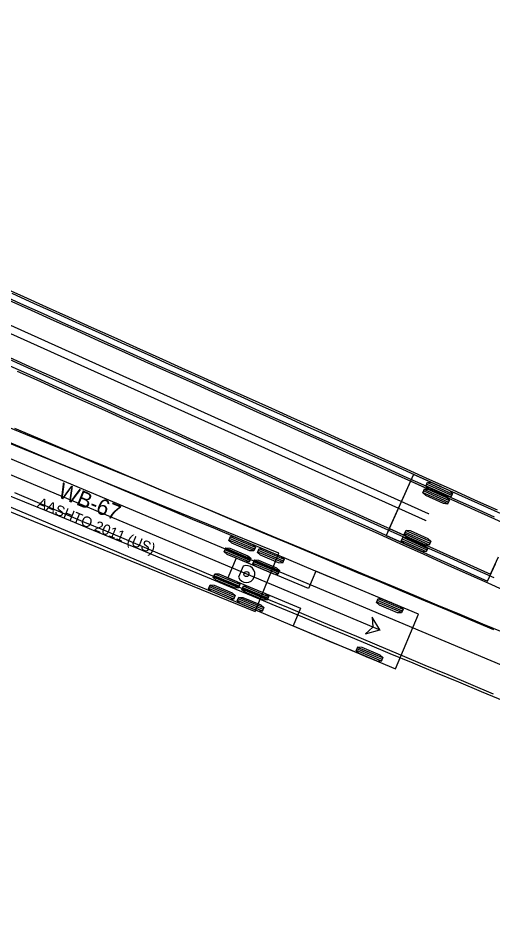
# Model space of a CAD drawing. Extents: x 916040 to 917457, y 328936 to 330267.
# Drawn here: x 917082.1 to 917146.2, y 329502 to 329623.8 of the extents above; entities that cross this region are included whole.
import ezdxf

# ---------------------------------------------------------------- set-up
doc = ezdxf.new("R2010")
doc.units = 0
for name, color, linetype in [('NB_RightontoRoute25_WB67', 7, 'Continuous'), ('NB_ThruontoManchester_WB67', 7, 'Continuous'), ('SB_LeftontoRoute25_WB67', 7, 'Continuous'), ('WB_LeftontoSaco_WB67', 7, 'Continuous'), ('WB_RightontoManchester_WB67', 7, 'Continuous'), ('WB_Thru_WB67', 7, 'Continuous')]:
    doc.layers.add(name, color=color, linetype=linetype)

msp = doc.modelspace()

# ---------------------------------------------------------------- linework, layer by layer
at = {"layer": 'NB_RightontoRoute25_WB67'}
msp.add_line((917062.28, 329572.24), (917451.54, 329408.71), dxfattribs=at)
for points in [[(917080.05, 329568.92), (917083.14, 329567.65), (917086.23, 329566.39), (917089.31, 329565.12), (917092.4, 329563.85), (917095.48, 329562.58), (917098.57, 329561.3), (917101.65, 329560.03), (917104.74, 329558.75), (917107.82, 329557.48), (917110.9, 329556.2), (917113.98, 329554.92), (917117.06, 329553.64), (917120.14, 329552.36), (917123.22, 329551.08), (917126.3, 329549.8), (917129.38, 329548.52), (917132.46, 329547.23), (917135.54, 329545.95), (917138.62, 329544.66), (917141.7, 329543.38), (917144.78, 329542.09), (917147.85, 329540.81)], [(917081.65, 329568.44), (917084.73, 329567.15), (917087.8, 329565.86), (917090.88, 329564.57), (917093.95, 329563.27), (917097.03, 329561.98), (917100.11, 329560.69), (917103.18, 329559.4), (917106.26, 329558.11), (917109.33, 329556.81), (917112.41, 329555.52), (917115.48, 329554.23), (917118.56, 329552.94), (917121.63, 329551.65), (917124.71, 329550.35), (917127.78, 329549.06), (917130.86, 329547.77), (917133.93, 329546.48), (917137.01, 329545.19), (917140.08, 329543.9), (917143.16, 329542.6), (917146.23, 329541.31)], [(917079.91, 329559.79), (917083, 329558.52), (917086.08, 329557.26), (917089.16, 329555.99), (917092.24, 329554.72), (917095.32, 329553.45), (917098.41, 329552.17), (917101.49, 329550.9), (917104.56, 329549.62), (917107.64, 329548.35), (917110.72, 329547.07), (917113.8, 329545.79), (917116.88, 329544.51), (917119.96, 329543.23), (917123.04, 329541.95), (917126.11, 329540.67), (917129.19, 329539.39), (917132.27, 329538.1), (917135.35, 329536.82), (917138.42, 329535.53), (917141.5, 329534.25), (917144.58, 329532.96), (917147.65, 329531.68)], [(917081.65, 329559.77), (917084.72, 329558.48), (917087.8, 329557.18), (917090.87, 329555.89), (917093.94, 329554.6), (917097.02, 329553.31), (917100.09, 329552.02), (917103.17, 329550.73), (917106.24, 329549.44), (917109.31, 329548.14), (917112.39, 329546.85), (917115.46, 329545.56), (917118.54, 329544.27), (917121.61, 329542.98), (917124.69, 329541.69), (917127.76, 329540.4), (917130.83, 329539.1), (917133.91, 329537.81), (917136.98, 329536.52), (917140.06, 329535.23), (917143.13, 329533.94), (917146.21, 329532.65)]]:
    msp.add_lwpolyline(points, dxfattribs=at)
at = {"layer": 'NB_ThruontoManchester_WB67'}
msp.add_line((917062.28, 329572.24), (917451.54, 329408.71), dxfattribs=at)
at = {"layer": 'SB_LeftontoRoute25_WB67'}
for p, q in [((917117.3, 329551.6), (917068.21, 329571.59)), ((917061.51, 329570.4), (917130.9, 329541.25)), ((917065.01, 329563.72), (917114.09, 329543.73)), ((917114.04, 329552.16), (917110.66, 329553.58)), ((917114.13, 329552.37), (917110.75, 329553.79)), ((917113.49, 329550.85), (917110.11, 329552.27)), ((917113.95, 329551.95), (917110.57, 329553.37)), ((917113.31, 329550.43), (917109.93, 329551.85)), ((917113.4, 329550.64), (917110.02, 329552.06)), ((917114.09, 329543.73), (917117.3, 329551.6)), ((917117.82, 329550.33), (917114.44, 329551.75)), ((917117.91, 329550.54), (917114.53, 329551.96)), ((917118, 329550.75), (917114.62, 329552.17)), ((917117.3, 329551.6), (917117.3, 329551.6)), ((917111.53, 329550.93), (917110.42, 329548.29)), ((917121.31, 329546.83), (917111.53, 329550.93)), ((917112.48, 329549.85), (917111.86, 329548.36)), ((917117.19, 329548.8), (917113.81, 329550.22)), ((917117.27, 329549.02), (917113.89, 329550.44)), ((917117.36, 329549.23), (917113.98, 329550.65)), ((917112.03, 329547.36), (917108.65, 329548.78)), ((917122.3, 329549.19), (917121.31, 329546.83)), ((917136.13, 329543.39), (917122.3, 329549.19)), ((917111.85, 329546.94), (917108.47, 329548.36)), ((917111.94, 329547.15), (917108.56, 329548.57)), ((917110.42, 329548.29), (917120.2, 329544.18)), ((917111.21, 329545.42), (917107.83, 329546.84)), ((917111.3, 329545.63), (917107.92, 329547.05)), ((917111.39, 329545.84), (917108.01, 329547.26)), ((917115.72, 329545.32), (917112.34, 329546.74)), ((917115.81, 329545.53), (917112.43, 329546.95)), ((917115.9, 329545.74), (917112.52, 329547.16)), ((917115.08, 329543.8), (917111.7, 329545.21)), ((917115.17, 329544.01), (917111.79, 329545.43)), ((917115.26, 329544.22), (917111.88, 329545.64)), ((917133.87, 329543.59), (917130.49, 329545.01)), ((917133.96, 329543.8), (917130.58, 329545.22)), ((917134.05, 329544.01), (917130.67, 329545.43)), ((917120.2, 329544.18), (917119.21, 329541.82)), ((917133.04, 329536.01), (917136.13, 329543.39)), ((917136.13, 329543.39), (917136.13, 329543.39)), ((917119.21, 329541.82), (917133.04, 329536.01)), ((917131.3, 329537.48), (917127.92, 329538.9)), ((917131.13, 329537.06), (917127.75, 329538.48)), ((917131.22, 329537.27), (917127.83, 329538.69))]:
    msp.add_line(p, q, dxfattribs=at)
for points in [[(917080.93, 329566.58), (917084.01, 329565.28), (917087.1, 329563.98), (917090.19, 329562.69), (917093.27, 329561.39), (917096.36, 329560.1), (917099.44, 329558.8), (917102.53, 329557.5), (917105.61, 329556.21), (917108.7, 329554.91), (917111.78, 329553.62), (917114.86, 329552.32), (917117.95, 329551.02), (917121.03, 329549.73), (917124.12, 329548.43), (917127.2, 329547.14), (917130.29, 329545.84), (917132.44, 329544.94)], [(917080.94, 329557.9), (917084.02, 329556.6), (917087.1, 329555.31), (917090.19, 329554.01), (917093.27, 329552.72), (917096.35, 329551.42), (917099.44, 329550.12), (917102.52, 329548.83), (917105.6, 329547.53), (917108.69, 329546.24), (917111.77, 329544.94), (917114.85, 329543.65), (917117.94, 329542.35), (917121.02, 329541.06), (917124.1, 329539.76), (917127.19, 329538.47), (917129.35, 329537.56)]]:
    msp.add_lwpolyline(points, dxfattribs=at)
for points in [[(917114.15, 329552.43), (917113.93, 329551.9), (917113.39, 329551.94), (917110.96, 329552.96), (917110.55, 329553.32), (917110.77, 329553.85), (917111.31, 329553.81), (917113.74, 329552.78)], [(917113.51, 329550.91), (917113.29, 329550.38), (917112.75, 329550.42), (917110.32, 329551.44), (917109.91, 329551.8), (917110.13, 329552.32), (917110.67, 329552.29), (917113.11, 329551.26)], [(917118.02, 329550.8), (917117.8, 329550.27), (917117.26, 329550.31), (917114.83, 329551.34), (917114.42, 329551.69), (917114.64, 329552.22), (917115.18, 329552.18), (917117.62, 329551.16)], [(917117.39, 329549.28), (917117.16, 329548.75), (917116.62, 329548.79), (917114.19, 329549.81), (917113.78, 329550.17), (917114, 329550.7), (917114.54, 329550.66), (917116.98, 329549.64)], [(917112.05, 329547.42), (917111.83, 329546.89), (917111.29, 329546.93), (917108.85, 329547.95), (917108.45, 329548.31), (917108.67, 329548.84), (917109.21, 329548.8), (917111.64, 329547.77)], [(917111.41, 329545.9), (917111.19, 329545.37), (917110.65, 329545.41), (917108.21, 329546.43), (917107.81, 329546.79), (917108.03, 329547.32), (917108.57, 329547.28), (917111, 329546.25)], [(917115.92, 329545.79), (917115.7, 329545.26), (917115.16, 329545.3), (917112.73, 329546.33), (917112.32, 329546.68), (917112.54, 329547.21), (917113.08, 329547.17), (917115.51, 329546.15)], [(917115.28, 329544.27), (917115.06, 329543.74), (917114.52, 329543.78), (917112.09, 329544.8), (917111.68, 329545.16), (917111.9, 329545.69), (917112.44, 329545.65), (917114.88, 329544.63)], [(917134.07, 329544.07), (917133.85, 329543.54), (917133.31, 329543.58), (917130.87, 329544.6), (917130.47, 329544.96), (917130.69, 329545.49), (917131.23, 329545.45), (917133.66, 329544.42)], [(917130.9, 329541.25), (917129.9, 329542.98), (917129.97, 329541.63), (917128.96, 329540.74)], [(917131.33, 329537.53), (917131.1, 329537.01), (917130.56, 329537.05), (917128.13, 329538.07), (917127.72, 329538.43), (917127.95, 329538.96), (917128.49, 329538.92), (917130.92, 329537.89)]]:
    msp.add_lwpolyline(points, close=True, dxfattribs=at)
for centre, radius in [((917112.92, 329548.79), 0.34), ((917132.44, 329544.94), 0.0417), ((917130.9, 329541.25), 0.0417), ((917129.35, 329537.56), 0.0417)]:
    msp.add_circle(centre, radius, dxfattribs=at)
msp.add_arc((917112.92, 329548.79), 1.14, 202.2286, 112.2286, dxfattribs=at)
at = {"layer": 'WB_LeftontoSaco_WB67'}
for p, q in [((917137.05, 329556.02), (916988.64, 329622.84)), ((917135.04, 329561.31), (917131.76, 329554.01)), ((917148.72, 329555.15), (917135.04, 329561.31)), ((917136.73, 329559.79), (917140.08, 329558.29)), ((917136.83, 329560), (917140.17, 329558.49)), ((917136.92, 329560.21), (917140.27, 329558.7)), ((917131.76, 329554.01), (917145.43, 329547.85)), ((917131.76, 329554.01), (917131.76, 329554.01)), ((917133.92, 329553.54), (917137.26, 329552.04)), ((917134.01, 329553.75), (917137.36, 329552.25)), ((917133.83, 329553.33), (917137.17, 329551.83)), ((917145.43, 329547.85), (917146.49, 329550.19))]:
    msp.add_line(p, q, dxfattribs=at)
for points in [[(917146.36, 329556.48), (917143.32, 329557.85), (917140.28, 329559.22), (917137.24, 329560.59), (917134.2, 329561.96), (917131.16, 329563.33), (917128.12, 329564.7), (917125.08, 329566.07), (917122.03, 329567.44), (917118.99, 329568.81), (917115.95, 329570.18), (917112.91, 329571.55), (917109.87, 329572.92), (917106.83, 329574.29), (917103.79, 329575.66), (917100.75, 329577.02), (917097.71, 329578.39), (917094.66, 329579.76), (917091.62, 329581.13), (917088.58, 329582.5), (917085.54, 329583.87), (917082.5, 329585.24), (917079.46, 329586.61)], [(917138.69, 329559.67), (917135.65, 329561.03), (917132.61, 329562.4), (917129.57, 329563.77), (917126.52, 329565.14), (917123.48, 329566.51), (917120.44, 329567.88), (917117.4, 329569.25), (917114.36, 329570.62), (917111.32, 329571.99), (917108.28, 329573.36), (917105.24, 329574.73), (917102.2, 329576.1), (917099.16, 329577.47), (917096.11, 329578.84), (917093.07, 329580.21), (917090.03, 329581.58), (917086.99, 329582.94), (917083.95, 329584.31), (917080.91, 329585.68)], [(917135.4, 329552.37), (917132.36, 329553.74), (917129.32, 329555.11), (917126.28, 329556.48), (917123.24, 329557.85), (917120.2, 329559.22), (917117.16, 329560.59), (917114.12, 329561.96), (917111.08, 329563.33), (917108.03, 329564.7), (917104.99, 329566.06), (917101.95, 329567.43), (917098.91, 329568.8), (917095.87, 329570.17), (917092.83, 329571.54), (917089.79, 329572.91), (917086.75, 329574.28), (917083.71, 329575.65), (917080.67, 329577.02)], [(917148.95, 329546), (917145.91, 329547.36), (917142.87, 329548.73), (917139.83, 329550.1), (917136.79, 329551.47), (917133.75, 329552.84), (917130.71, 329554.21), (917127.67, 329555.58), (917124.63, 329556.95), (917121.59, 329558.32), (917118.54, 329559.69), (917115.5, 329561.06), (917112.46, 329562.43), (917109.42, 329563.8), (917106.38, 329565.17), (917103.34, 329566.54), (917100.3, 329567.9), (917097.26, 329569.27), (917094.22, 329570.64), (917091.17, 329572.01), (917088.13, 329573.38), (917085.09, 329574.75), (917082.05, 329576.12)]]:
    msp.add_lwpolyline(points, dxfattribs=at)
for points in [[(917136.71, 329559.74), (917136.95, 329560.26), (917137.49, 329560.21), (917139.89, 329559.12), (917140.29, 329558.76), (917140.05, 329558.23), (917139.52, 329558.29), (917137.11, 329559.37)], [(917133.8, 329553.28), (917134.04, 329553.8), (917134.58, 329553.75), (917136.98, 329552.66), (917137.38, 329552.3), (917137.15, 329551.78), (917136.61, 329551.83), (917134.2, 329552.91)]]:
    msp.add_lwpolyline(points, close=True, dxfattribs=at)
for centre in [(917138.69, 329559.67), (917137.05, 329556.02), (917135.4, 329552.37)]:
    msp.add_circle(centre, 0.0417, dxfattribs=at)
at = {"layer": 'WB_RightontoManchester_WB67'}
for p, q in [((917137.46, 329556.93), (916989.05, 329623.75)), ((917135.45, 329562.22), (917132.17, 329554.93)), ((917149.13, 329556.06), (917135.45, 329562.22)), ((917137.24, 329560.91), (917140.58, 329559.41)), ((917137.33, 329561.12), (917140.68, 329559.62)), ((917137.15, 329560.7), (917140.49, 329559.2)), ((917132.17, 329554.93), (917145.84, 329548.77)), ((917132.17, 329554.93), (917132.17, 329554.93)), ((917134.24, 329554.24), (917137.58, 329552.74)), ((917134.33, 329554.45), (917137.67, 329552.95)), ((917134.43, 329554.66), (917137.77, 329553.16)), ((917145.84, 329548.77), (917146.9, 329551.11))]:
    msp.add_line(p, q, dxfattribs=at)
for points in [[(917146.77, 329557.4), (917143.73, 329558.77), (917140.69, 329560.14), (917137.65, 329561.5), (917134.61, 329562.87), (917131.57, 329564.24), (917128.53, 329565.61), (917125.49, 329566.98), (917122.44, 329568.35), (917119.4, 329569.72), (917116.36, 329571.09), (917113.32, 329572.46), (917110.28, 329573.83), (917107.24, 329575.2), (917104.2, 329576.57), (917101.16, 329577.94), (917098.12, 329579.31), (917095.08, 329580.68), (917092.03, 329582.04), (917088.99, 329583.41), (917085.95, 329584.78), (917082.91, 329586.15), (917079.87, 329587.52)], [(917139.1, 329560.58), (917136.06, 329561.95), (917133.02, 329563.32), (917129.98, 329564.69), (917126.94, 329566.05), (917123.89, 329567.42), (917120.85, 329568.79), (917117.81, 329570.16), (917114.77, 329571.53), (917111.73, 329572.9), (917108.69, 329574.27), (917105.65, 329575.64), (917102.61, 329577.01), (917099.57, 329578.38), (917096.52, 329579.75), (917093.48, 329581.12), (917090.44, 329582.49), (917087.4, 329583.86), (917084.36, 329585.23), (917081.32, 329586.6)], [(917146.32, 329548.28), (917143.28, 329549.65), (917140.24, 329551.02), (917137.2, 329552.38), (917134.16, 329553.75), (917131.12, 329555.12), (917128.08, 329556.49), (917125.04, 329557.86), (917122, 329559.23), (917118.95, 329560.6), (917115.91, 329561.97), (917112.87, 329563.34), (917109.83, 329564.71), (917106.79, 329566.08), (917103.75, 329567.45), (917100.71, 329568.82), (917097.67, 329570.19), (917094.63, 329571.56), (917091.59, 329572.92), (917088.54, 329574.29), (917085.5, 329575.66), (917082.46, 329577.03), (917079.42, 329578.4)], [(917135.81, 329553.28), (917132.77, 329554.65), (917129.73, 329556.02), (917126.69, 329557.39), (917123.65, 329558.76), (917120.61, 329560.13), (917117.57, 329561.5), (917114.53, 329562.87), (917111.49, 329564.24), (917108.45, 329565.61), (917105.4, 329566.98), (917102.36, 329568.35), (917099.32, 329569.72), (917096.28, 329571.08), (917093.24, 329572.45), (917090.2, 329573.82), (917087.16, 329575.19), (917084.12, 329576.56), (917081.08, 329577.93)]]:
    msp.add_lwpolyline(points, dxfattribs=at)
for points in [[(917137.12, 329560.65), (917137.36, 329561.17), (917137.9, 329561.12), (917140.3, 329560.04), (917140.7, 329559.67), (917140.47, 329559.15), (917139.93, 329559.2), (917137.52, 329560.28)], [(917134.21, 329554.19), (917134.45, 329554.71), (917134.99, 329554.66), (917137.39, 329553.58), (917137.79, 329553.21), (917137.56, 329552.69), (917137.02, 329552.74), (917134.61, 329553.82)]]:
    msp.add_lwpolyline(points, close=True, dxfattribs=at)
for centre in [(917139.1, 329560.58), (917137.46, 329556.93), (917135.81, 329553.28)]:
    msp.add_circle(centre, 0.0417, dxfattribs=at)
at = {"layer": 'WB_Thru_WB67'}
for p, q in [((917137.05, 329556.02), (916988.64, 329622.84)), ((917135.04, 329561.31), (917131.76, 329554.01)), ((917148.72, 329555.15), (917135.04, 329561.31)), ((917136.73, 329559.79), (917140.08, 329558.29)), ((917136.83, 329560), (917140.17, 329558.49)), ((917136.92, 329560.21), (917140.27, 329558.7)), ((917131.76, 329554.01), (917145.43, 329547.85)), ((917131.76, 329554.01), (917131.76, 329554.01)), ((917133.92, 329553.54), (917137.26, 329552.04)), ((917134.01, 329553.75), (917137.36, 329552.25)), ((917133.83, 329553.33), (917137.17, 329551.83)), ((917145.43, 329547.85), (917146.49, 329550.19))]:
    msp.add_line(p, q, dxfattribs=at)
for points in [[(917146.36, 329556.48), (917143.32, 329557.85), (917140.28, 329559.22), (917137.24, 329560.59), (917134.2, 329561.96), (917131.16, 329563.33), (917128.12, 329564.7), (917125.08, 329566.07), (917122.03, 329567.44), (917118.99, 329568.81), (917115.95, 329570.18), (917112.91, 329571.55), (917109.87, 329572.92), (917106.83, 329574.29), (917103.79, 329575.66), (917100.75, 329577.02), (917097.71, 329578.39), (917094.66, 329579.76), (917091.62, 329581.13), (917088.58, 329582.5), (917085.54, 329583.87), (917082.5, 329585.24), (917079.46, 329586.61)], [(917138.69, 329559.67), (917135.65, 329561.03), (917132.61, 329562.4), (917129.57, 329563.77), (917126.52, 329565.14), (917123.48, 329566.51), (917120.44, 329567.88), (917117.4, 329569.25), (917114.36, 329570.62), (917111.32, 329571.99), (917108.28, 329573.36), (917105.24, 329574.73), (917102.2, 329576.1), (917099.16, 329577.47), (917096.11, 329578.84), (917093.07, 329580.21), (917090.03, 329581.58), (917086.99, 329582.94), (917083.95, 329584.31), (917080.91, 329585.68)], [(917135.4, 329552.37), (917132.36, 329553.74), (917129.32, 329555.11), (917126.28, 329556.48), (917123.24, 329557.85), (917120.2, 329559.22), (917117.16, 329560.59), (917114.12, 329561.96), (917111.08, 329563.33), (917108.03, 329564.7), (917104.99, 329566.06), (917101.95, 329567.43), (917098.91, 329568.8), (917095.87, 329570.17), (917092.83, 329571.54), (917089.79, 329572.91), (917086.75, 329574.28), (917083.71, 329575.65), (917080.67, 329577.02)], [(917148.95, 329546), (917145.91, 329547.36), (917142.87, 329548.73), (917139.83, 329550.1), (917136.79, 329551.47), (917133.75, 329552.84), (917130.71, 329554.21), (917127.67, 329555.58), (917124.63, 329556.95), (917121.59, 329558.32), (917118.54, 329559.69), (917115.5, 329561.06), (917112.46, 329562.43), (917109.42, 329563.8), (917106.38, 329565.17), (917103.34, 329566.54), (917100.3, 329567.9), (917097.26, 329569.27), (917094.22, 329570.64), (917091.17, 329572.01), (917088.13, 329573.38), (917085.09, 329574.75), (917082.05, 329576.12)]]:
    msp.add_lwpolyline(points, dxfattribs=at)
for points in [[(917136.71, 329559.74), (917136.95, 329560.26), (917137.49, 329560.21), (917139.89, 329559.12), (917140.29, 329558.76), (917140.05, 329558.23), (917139.52, 329558.29), (917137.11, 329559.37)], [(917133.8, 329553.28), (917134.04, 329553.8), (917134.58, 329553.75), (917136.98, 329552.66), (917137.38, 329552.3), (917137.15, 329551.78), (917136.61, 329551.83), (917134.2, 329552.91)]]:
    msp.add_lwpolyline(points, close=True, dxfattribs=at)
for centre in [(917138.69, 329559.67), (917137.05, 329556.02), (917135.4, 329552.37)]:
    msp.add_circle(centre, 0.0417, dxfattribs=at)

# ---------------------------------------------------------------- texts
at = {"layer": 'SB_LeftontoRoute25_WB67'}
for s, height, p in [('WB-67', 2.125, (917087.36, 329559.21)), ('AASHTO 2011 (US)', 1.4167, (917084.59, 329557.85))]:
    msp.add_text(s, height=height, rotation=337.8356, dxfattribs=at).set_placement(p)

doc.saveas('drawing.dxf')
